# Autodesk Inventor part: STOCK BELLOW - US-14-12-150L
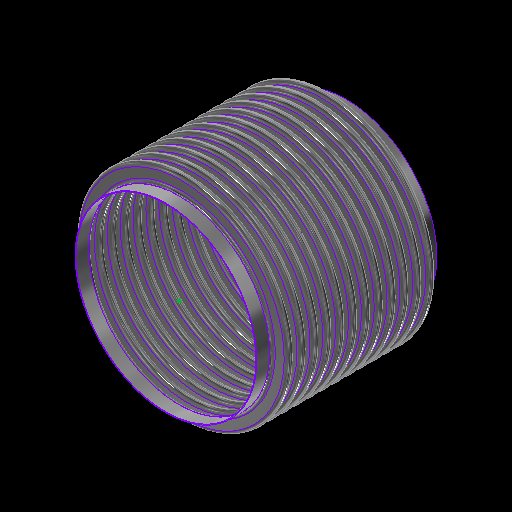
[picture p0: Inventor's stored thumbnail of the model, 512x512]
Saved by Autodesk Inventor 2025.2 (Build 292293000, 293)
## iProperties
Category: 16 GA (0.060 THICK)
RuleStatus: InUse
Created: 2024-01
Part Number: STOCK BELLOW - US-14-12-150L
Project: =STOCK BELLOWS: <Stock Number><SFILL>
Material: ASTM A240-304
Description: =STOCK BELLOWS: <Stock Number>, <SID_> I.D., <SOD_> O.D., <SPLY_> PLY, <Category>, <SNET_CONS> CONS.<PITCH_><STANGENT_> TANGENT<SFILL>
Document SubType Name: Sheet Metal
Designer: GS
Stock Number: U.S-14-12-150L
Surface Area: 23132.1 cm^2
Volume: 1754.85 cm^3
Sheet Metal Rule: Default
Appearance: STAINLESS STEEL
Mass: 14139.3 g
Density: 8.05729 g/cm^3
THK: 0.036
ID: 3.500
OD: 4.250
CONS_: 2
PITCH: 0.500
TANGENT: 0.500
BELLOWS_UPSET: 0.000
d79: 1.000
d82: 1.000
d83: 26.000
d84: 24.000
d174: 8
d214: 8
STHK_: 0.060
SID_: 14.000
SOD_: 16.500
SPITCH_: 1.000
STANGENT__: 1.000
SBELLOWS_UPSET_: 0.000
SDIFF_TAN: 1.000
d252: 2
d275: 2
d287: 0.050
d289: 0.500
d290: 0.000
SOD_NECK: 14 1/8
PLY: 1
PSET: 4.178
PBAR: 1.035
COUNTER: 1.500
NET_TUBE: 3.071
CONS: 2
S_CONS: 0
NET_CONS: 2
ID_M: 88.90 mm
OD_M: 107.95 mm
THK_M: 0.91 mm
ID_U: 3.500 in
OD_U: 4.250 in
THK_U: 0.036 in
TANGENT2: 0.500
TAN_TO_TAN: 1.000 in
d80: 2.571
d81: 10
SID: 2.375
SCONS_: 12
SPITCH: 0.250
STANGENT_: 1.000
SBELLOWS_UPSET: 0.000
SNET_CONS: 12
SS_CONS: 0
SCONS: 8
d190: 8
d191: 1
d192: 1
d193: 8
d194: 0
SIZE: 14.00
PRESSURE: 150
d230: 8
STANGENT: 4.000
SPLY_: 1
d233: 8
d234: 0
d263: 2
d265: 1
d268: 2
d269: 0
d286: 2
d288: 1
d291: 2
d292: 0
SREROLL: 0.750
BLETP: 1.000 ul
PRES_Copy: 85
MATTABLE: 20 GA (0.036 THICK)
PART_NUMBER: U.S-14-12-150L
PITCH_: =, <SPITCH_> PITCH,
CFILL: .
SFILL: .
MESH: ,
COMP: 2.3
EXT: 1.15
LAT: 0.60
ANG: 573
ASR: 2596
LSR: 5659
ANSR: 1185
PRES: 150
COMPM: 23.0
EXTM: 11.5
LATM: 6.00
ASRM: 454.637
PRESM: 10.342
LSRM: 991.061
ANSRM: 207.529
TEMPMIN: 20
TEMPMAX: 800
TEMPMINM: -7
TEMPMAXM: 427
WEIGHTM: 14.139
WEIGHT: 31.172
Author: GS
Keywords: 20 GA (0.036 THICK)
Comments: =STOCK BELLOW - <STOCK NUMBER>
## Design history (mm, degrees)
sketch "Sketch2"
  geometry: L1 (0, -177.245)-(0, 562.856) reference; L2 (45.364, 0)-(44.45, 0); L3 (48.082, -2.718)-(50.343, -2.718); L4 (48.082, -3.632)-(50.343, -3.632); L5 (50.343, -9.982)-(48.082, -9.982); L6 (50.343, -9.068)-(48.082, -9.068); L7 (45.364, -12.7)-(44.45, -12.7); L8 (48.082, 0)-(48.082, -12.7); L9 (50.343, -6.35)-(53.975, -6.35); L10 (44.45, 0)-(44.45, -12.7); L11 (20.376, 102.841)-(20.376, 101.926); L12 (58.262, 457.127)-(58.262, 349.177); L13 (58.262, 444.427)-(58.262, 336.477); L14 (93.133, -58.817)-(93.133, -71.517); L15 (118.746, -66.401)-(118.746, -66.401); L16 (50.343, -9.068)-(50.343, -9.982); L17 (48.082, -9.068)-(48.082, -9.982); L18 (48.082, -9.525)-(50.343, -9.525); L19 (53.975, 0)-(53.975, -12.7); L20 (-50.343, -9.068)-(-50.343, -9.982); L21 (-50.343, -2.718)-(-48.082, -2.718); L22 (-50.343, -3.632)-(-48.082, -3.632); L23 (-48.082, -9.068)-(-50.343, -9.068); L24 (-50.343, -9.525)-(-48.082, -9.525); L25 (-48.082, -9.982)-(-50.343, -9.982); L26 (-48.082, -9.068)-(-48.082, -9.982); L27 (-44.45, 0.653)-(-44.45, -12.047); L28 (-48.082, -6.35)-(-44.45, -6.35); L29 (-50.343, 0.653)-(-50.343, -12.7); L30 (-53.061, 0)-(-53.975, 0); L31 (-53.975, 0)-(-53.975, -12.7); L32 (-53.061, -12.7)-(-53.975, -12.7); A1 r 2.718 centre (48.082, 0) between (45.364, 0) and (48.082, -2.718); A2 r 3.632 centre (48.082, 0) between (44.45, 0) and (48.082, -3.632); A3 r 3.632 centre (50.343, -6.35) between (50.343, -9.982) and (50.343, -2.718); A4 r 2.718 centre (50.343, -6.35) between (50.343, -9.068) and (50.343, -3.632); A5 r 2.718 centre (48.082, -12.7) between (48.082, -9.982) and (45.364, -12.7); A6 r 3.632 centre (48.082, -12.7) between (48.082, -9.068) and (44.45, -12.7); A7 r 3.175 centre (50.343, -6.35) between (50.343, -9.525) and (53.518, -6.35); A8 r 3.175 centre (48.082, -12.7) between (48.082, -9.525) and (44.907, -12.7); A9 r 2.718 centre (-50.343, -12.7) between (-50.343, -9.982) and (-53.061, -12.7); A10 r 2.718 centre (-48.082, -6.35) between (-48.082, -9.068) and (-48.082, -3.632); A11 r 3.175 centre (-48.082, -6.35) between (-48.082, -9.525) and (-44.907, -6.35); A12 r 3.632 centre (-48.082, -6.35) between (-48.082, -9.982) and (-48.082, -2.718); A13 r 3.175 centre (-50.343, -12.7) between (-50.343, -9.525) and (-53.518, -12.7); A14 r 3.632 centre (-50.343, -12.7) between (-50.343, -9.068) and (-53.975, -12.7); A15 r 2.718 centre (-50.343, 0) between (-53.061, 0) and (-50.343, -2.718); A16 r 3.632 centre (-50.343, 0) between (-53.975, 0) and (-50.343, -3.632); 10 further points
  constraints: 62 end point, 38 point on circle, 20 tangent, 16 centre point, 12 parallel, 9 midpoint, 7 vertical, 6 coincident, 6 concentric, 6 point on line, 4 equal radius, 4 perpendicular, 3 horizontal, 1 collinear, 1 horizontal alignment, 10 other
  dimensions: "THK" = 0.9144 distance of L11.start L11.end; "ID" = 88.9 distance of L11.end point (20.376, 13.026); "OD" = 107.95 distance of L12.start L12.end; "PITCH" = 12.7 distance of L12.start L13.start; "TANGENT" = 12.7 distance of L14.start L14.end; "BELLOWS_UPSET" = 0 distance of L15.start L15.end; "d43" = 88.9 diameter of L10 L1 (= ID); "d44" = 107.95 diameter of L9.end L1 (= OD); "d45" = 0.9144 distance between parallel lines of L5 L6 (computed from THK, PLY); "d46" = 3.6322 radius of A3 (computed from PITCH, THK, PLY); "UPSET_PITCH" = 12.7 distance of L2.end L7.end (derived); "SIDEWALL_ANGLE" = 360 deg dimension on L3 L9 (derived); "CON_GAP" = 5.4356 distance of point (48.082, -9.068) point (48.082, -3.632) (derived); "TAN1" = 4.98728 dimension on A8 (derived); "TAN2" = 4.98728 dimension on A7 (derived); "LEG1" = 2.2606 distance of L18.start L18.end (derived); "d278" = 0.9144 distance between parallel lines of L25 L23 (derived); "d279" = 3.6322 radius of A12 (derived); "d280" = 12.7 distance of L30.end L31.end (derived); "d281" = 360 deg dimension on L21 L28 (derived); "d282" = 5.4356 distance of point (-50.343, -9.068) point (-50.343, -3.632) (derived); "d283" = 4.98728 dimension on A13 (derived); "d284" = 4.98728 dimension on A11 (derived); "d285" = 2.2606 distance of L24.start L24.end (derived); "d293" = 88.9 diameter of L27 L1 (derived); "d294" = 107.95 diameter of L31 L1 (derived)
  node "Sketch Rectangular Pattern1" dims "d31" = 25.4, "ID" = 88.9
  node "Sketch Rectangular Pattern2" dims "d39" = 25.4, "PITCH" = 12.7
revolve "CONS" stored, may be unused: angle "d48" = 90 deg
node "BELLOW MIDPLANE"
pattern_linear "Rectangular Pattern2" dims "d52" = 12.7 (= UPSET_PITCH)
sketch "Sketch5"
  geometry: C1 r 45.364 at (0, 0) reference; C2 r 44.45 at (0, 0) reference
extrude "TANGENT" new body sketch "Sketch5" distance "d53" = 12.7 (= TANGENT); taper "d54" = 0 deg
revolve "SAMETAN" stored, may be unused: angle "d65" = 90 deg
revolve "DIFFTAN" stored, may be unused: angle "d70" = 90 deg
sketch "Sketch9"
  geometry: L1 (53.319, 0)-(-53.319, 0) reference; L2 (0, -17.78)-(0, 17.78) reference; L3 (38.085, 0)-(-38.085, 0); L4 (38.085, -11.906)-(38.085, 11.906); L5 (25.385, -11.906)-(25.385, 11.906); L6 (13.15, 11.906)-(13.15, -11.906); L7 (-25.385, -11.906)-(-25.385, 11.906); L8 (-38.085, -11.906)-(-38.085, 11.906); L9 (37.291, -11.906)-(37.291, 11.906); L10 (38.085, -11.906)-(37.291, -11.906); L11 (38.085, 11.906)-(37.291, 11.906); L12 (13.546, 11.906)-(12.753, 11.906); L13 (12.753, 11.906)-(12.753, -11.906); L14 (12.753, -11.906)-(13.546, -11.906); L15 (13.546, -11.906)-(13.546, 11.906); L16 (-13.546, 11.906)-(-13.546, -11.906); L17 (-13.15, 11.906)-(-13.15, -11.906); L18 (-13.546, -11.906)-(-12.753, -11.906); L19 (-12.753, -11.906)-(-12.753, 11.906); L20 (-12.753, 11.906)-(-13.546, 11.906); L21 (-38.085, -11.906)-(-37.291, -11.906); L22 (-37.291, -11.906)-(-37.291, 11.906); L23 (-37.291, 11.906)-(-38.085, 11.906); L24 (-38.085, 11.906)-(-38.085, -11.906); L25 (38.085, -0.397)-(-38.085, -0.397); L26 (-38.085, -0.397)-(-38.085, 0.397); L27 (-38.085, 0.397)-(38.085, 0.397); L28 (38.085, 0.397)-(38.085, -0.397); L29 (-38.085, 11.906)-(38.085, 11.906); L30 (38.085, 11.906)-(38.085, 12.7); L31 (38.085, 12.7)-(-38.085, 12.7); L32 (-38.085, 12.7)-(-38.085, 11.906); L33 (38.085, -11.906)-(-38.085, -11.906); L34 (-38.085, -11.906)-(-38.085, -12.7); L35 (-38.085, -12.7)-(38.085, -12.7); L36 (38.085, -12.7)-(38.085, -11.906); 30 further points
  constraints: 68 end point, 13 midpoint, 13 parallel, 8 horizontal, 7 perpendicular, 6 equal length, 3 point on line, 2 vertical, 14 other
  dimensions: "d115" = 23.8125 distance of L4.start L4.end (derived); "d116" = 12.7 distance between parallel lines of L4 L5 (derived); "d117" = 12.23516 distance between parallel lines of L5 L6 (derived); "d125" = 38.53427 distance between parallel lines of L7 L6 (derived); "d127" = 12.7 distance between parallel lines of L8 L7 (derived); "d128" = 24.93516 distance between parallel lines of L6 L4 (derived); "d130" = 76.16943 distance between parallel lines of L8 L4 (derived); "RULER_THK" = 0.79375 distance between parallel lines of L4 L9; "d135" = 0.79375 distance of L13.end L14.end (derived); "d138" = 26.29911 distance of L13.end L16.end (derived); "d143" = 0.79375 distance of L22.end L8.end (derived); "d144" = 0.79375 distance between parallel lines of L27 L25 (derived)
extrude "RULER" join sketch "Sketch9" distance "d149" = 0.79375 (derived); taper "d150" = 0 deg
extrude "BARS" join sketch "Sketch9" distance "d151" = 0.79375 (derived); taper "d152" = 0 deg
pattern_linear "Rectangular Pattern4" dims "d155" = 26.29911 (derived)
sketch "Sketch13"
  geometry: L1 (93.149, -52.467)-(93.149, -77.867); L2 (179.324, 0)-(177.8, 0); L3 (179.324, -25.4)-(177.8, -25.4); L4 (202.438, -19.812)-(184.912, -19.812); L5 (202.438, -18.288)-(184.912, -18.288); L6 (202.438, -12.7)-(209.55, -12.7); L7 (184.912, -5.588)-(202.438, -5.588); L8 (184.912, 0)-(184.912, -25.4); L9 (177.8, 0)-(177.8, -25.4); L10 (58.254, -77.331)-(58.254, -496.431); L11 (58.254, -102.731)-(58.254, -521.831); L12 (58.254, -153.531)-(58.254, -572.631); L13 (58.254, -178.931)-(58.254, -598.031); L14 (58.254, -204.331)-(58.254, -623.431); L15 (58.254, -229.731)-(58.254, -648.831); L16 (58.254, -255.131)-(58.254, -674.231); L17 (58.254, -128.131)-(58.254, -547.231); L18 (20.376, 103.45)-(20.376, 101.926); L19 (184.912, -7.112)-(202.438, -7.112); L20 (0, -829.767)-(0, 258.986) reference; L21 (-41.91, 0)-(251.46, 0) reference; A1 r 5.588 centre (184.912, 0) between (179.324, 0) and (184.912, -5.588); A2 r 5.588 centre (184.912, -25.4) between (184.912, -19.812) and (179.324, -25.4); A3 r 7.112 centre (184.912, -25.4) between (184.912, -18.288) and (177.8, -25.4); A4 r 5.588 centre (202.438, -12.7) between (202.438, -18.288) and (202.438, -7.112); A5 r 7.112 centre (202.438, -12.7) between (202.438, -19.812) and (202.438, -5.588); A6 r 7.112 centre (184.912, 0) between (177.8, 0) and (184.912, -7.112); 6 further points; 1 other entity
  constraints: 38 end point, 15 point on circle, 9 tangent, 6 centre point, 6 parallel, 5 vertical alignment, 4 point on line, 4 vertical, 3 coincident, 3 concentric, 2 collinear, 2 equal radius, 1 horizontal, 1 perpendicular, 23 other
  dimensions: "SBELLOWS_UPSET_" = 0 distance of point (118.762, -66.401) point (118.762, -66.401); "STOTAL_THK_BELLOW__" = 1.524 distance between parallel lines of L4 L5 (derived); "d224" = 7.112 radius of A5 (derived); "d225" = 25.4 distance of L2.end L3.end (derived); "SSIDEWALL_ANGLE_" = 360 deg dimension on L7 L6 (derived); "SSCON_GAP_" = 11.176 distance of point (184.912, -18.288) point (184.912, -7.112) (derived); "d235" = 355.6 diameter of L9 L20 (derived); "d236" = 419.1 diameter of L6.end L20 (derived)
  node "Sketch Rectangular Pattern4" dims "d228" = 25.4
  node "Sketch Rectangular Pattern5" dims "d229" = 25.4
revolve "SBELLOW" stored, may be unused: angle "d197" = 90 deg
pattern_linear "Rectangular Pattern5" dims "d204" = 25.4 (derived)
revolve "STANGENT" stored, may be unused: angle "d240" = 90 deg
revolve "SSAMETAN" stored, may be unused: angle "d241" = 90 deg
revolve "SDIFFTAN" stored, may be unused: angle "d246" = 90 deg
revolve "INVCON" stored, may be unused: angle "d295" = 90 deg
pattern_linear "Rectangular Pattern6" dims "d298" = 12.7 (derived)
revolve "INVTANGENT" stored, may be unused: angle "d302" = 90 deg
revolve "INVSAMETAN" stored, may be unused: angle "d307" = 90 deg
revolve "INVDIFFTAN" stored, may be unused: angle "d312" = 90 deg
sketch "ID BELLOW MOUNT CALC"
  geometry: L1 (44.45, 0)-(38.1, 0); L2 (38.1, 0)-(38.1, 12.7); L3 (38.1, 12.7)-(44.45, 12.7); L4 (44.45, 12.7)-(44.45, 0); L5 (36.513, 12.7)-(35.598, 12.7); L6 (35.598, 12.7)-(35.598, 0); L7 (35.598, 0)-(36.513, 0); L8 (36.513, 0)-(36.513, 12.7); L9 (0, -2.54)-(0, 15.24) reference; L10 (-8.89, 0)-(53.34, 0) reference; 1 further point
  constraints: 16 end point, 5 parallel, 2 collinear, 2 horizontal, 2 perpendicular
  dimensions: "d314" = 12.7 distance of L5.end L6.end (derived); "d315" = 0.9144 distance of L5.start L5.end (derived); "IG" = 1.5875 distance between parallel lines of L2 L8; "PIPE_OD" = 88.9 diameter of L4 L9; "PIPE_WALL" = 6.35 distance of L2.end L3.end; "ID_MT_BELLOW" = 71.1962 diameter of L6 L9 (derived)
revolve "CFILL" stored, may be unused: angle "d320" = 90 deg
pattern_linear "Rectangular Pattern7" dims "d323" = 12.7 (derived)
revolve "SFILL" stored, may be unused: angle "d324" = 90 deg
pattern_linear "Rectangular Pattern8" dims "d327" = 25.4 (derived)
node "STOCK BELLOW MIDPLANE"
node "BELLOW"
sketch "Sketch6"
  geometry: L1 (-12.7, 45.364)-(0, 45.364); L2 (0, 45.364)-(0, 44.45); L3 (0, 44.45)-(-12.7, 44.45); L4 (-12.7, 44.45)-(-12.7, 45.364); L5 (10.16, 0)-(-60.96, 0) reference; L6 (-38.1, -89.422)-(-38.1, 153.44) reference; 1 further point
  constraints: 8 end point, 2 parallel, 1 horizontal, 1 perpendicular
  dimensions: "d61" = 12.7 distance of L2.end L3.end (derived); "d62" = 0.9144 distance of L1.end L2.end (derived); "d63" = 88.9 diameter of L3 L5 (derived); "d64" = 25.4 distance between parallel lines of L4 L6 (derived)
sketch "Sketch12"
  geometry: 1 further point
sketch "Sketch14"
  geometry: L1 (-25.4, 179.324)-(0, 179.324); L2 (0, 179.324)-(0, 177.8); L3 (0, 177.8)-(-25.4, 177.8); L4 (-25.4, 177.8)-(-25.4, 179.324); L5 (5.08, 0)-(-30.48, 0) reference; L6 (0, -35.865)-(0, 215.189) reference; 1 further point
  constraints: 8 end point, 2 parallel, 1 collinear, 1 horizontal, 1 perpendicular
  dimensions: "d237" = 1.524 distance of L3.end L1.start (derived); "d238" = 355.6 diameter of L3 L5 (derived); "d239" = 25.4 distance of L1.start L1.end (derived); "SOD_NECK" = 358.648 diameter of L1 L5 (derived)
sketch "Sketch15"
  geometry: L1 (-35.865, 0)-(215.189, 0) reference; L2 (177.8, -304.8)-(179.324, -304.8); L3 (179.324, -304.8)-(179.324, -330.2); L4 (179.324, -330.2)-(177.8, -330.2); L5 (177.8, -330.2)-(177.8, -304.8); L6 (0, -398.78)-(0, 81.28) reference; 1 further point
  constraints: 8 end point, 2 parallel, 1 horizontal, 1 perpendicular
  dimensions: "d205" = 25.4 distance of L4.end L2.start (derived); "d206" = 1.524 distance of L3.end L4.end (derived); "d207" = 355.6 diameter of L5 L6 (derived); "d208" = 304.8 distance between parallel lines of L1 L2 (derived)
node "TANGENT_"
node "SAME_TAN"
sketch "Sketch8"
  geometry: L1 (45.364, -25.4)-(44.45, -25.4); L2 (44.45, -25.4)-(44.45, -38.1); L3 (44.45, -38.1)-(45.364, -38.1); L4 (45.364, -38.1)-(45.364, -25.4); L5 (0, -48.26)-(0, 22.86) reference; L6 (-89.422, 0)-(153.44, 0) reference; 1 further point
  constraints: 8 end point, 2 parallel, 1 horizontal, 1 perpendicular
  dimensions: "d66" = 88.9 diameter of L2 L5 (derived); "TOTAL_THK_BELLOW" = 0.9144 distance of L2.end L3.end (derived); "d68" = 25.4 distance between parallel lines of L1 L6 (derived); "d69" = 12.7 distance of L1.end L2.end (derived)
node "DIFF_TAN"
node "Sketch Rectangular Pattern3" dims "d138" = 26.29911 (derived), "d141" = 25.4
node "SBELLOW_"
node "STANGENT_"
node "SSAME_TAN"
sketch "Sketch16"
  geometry: L1 (179.324, -304.8)-(177.8, -304.8); L2 (177.8, -304.8)-(177.8, -330.2); L3 (177.8, -330.2)-(179.324, -330.2); L4 (179.324, -330.2)-(179.324, -304.8); L5 (0, -398.78)-(0, 81.28) reference; L6 (-35.865, 0)-(215.189, 0) reference; 1 further point
  constraints: 8 end point, 2 parallel, 1 horizontal, 1 perpendicular
  dimensions: "SDIFF_TAN" = 25.4 distance of L3.end L1.start; "d243" = 1.524 distance of L2.end L3.end (derived); "d244" = 304.8 distance between parallel lines of L1 L6 (derived); "d245" = 355.6 diameter of L2 L5 (derived)
node "SDIFF_TAN"
body "Solid15"
sketch "Sketch17"
  geometry: L1 (53.975, 12.7)-(53.061, 12.7); L2 (53.061, 12.7)-(53.061, 0); L3 (53.061, 0)-(53.975, 0); L4 (53.975, 0)-(53.975, 12.7); L5 (0, -2.54)-(0, 15.24) reference; L6 (-10.795, 0)-(64.77, 0) reference; 2 further points
  constraints: 8 end point, 2 parallel, 1 horizontal, 1 midpoint, 1 perpendicular, 1 point on line
  dimensions: "INVTANGENT" = 12.7 distance of L3.end L1.start (derived); "d300" = 0.9144 distance of L1.start L1.end (derived); "d301" = 107.95 diameter of L4 L5 (derived)
body "Solid16"
sketch "Sketch18"
  geometry: L1 (53.975, -25.4)-(53.061, -25.4); L2 (53.061, -25.4)-(53.061, -38.1); L3 (53.061, -38.1)-(53.975, -38.1); L4 (53.975, -38.1)-(53.975, -25.4); L5 (-10.795, 0)-(64.77, 0) reference; L6 (0, -48.26)-(0, 22.86) reference; 1 further point
  constraints: 8 end point, 2 parallel, 1 horizontal, 1 perpendicular
  dimensions: "d303" = 25.4 distance between parallel lines of L1 L5 (derived); "d304" = 12.7 distance of L3.end L1.start (derived); "d305" = 0.9144 distance of L2.end L3.end (derived); "d306" = 107.95 diameter of L4 L6 (derived)
body "Solid17"
sketch "Sketch19"
  geometry: L1 (53.975, -25.4)-(53.061, -25.4); L2 (53.061, -25.4)-(53.061, -38.1); L3 (53.061, -38.1)-(53.975, -38.1); L4 (53.975, -38.1)-(53.975, -25.4); L5 (0, -48.26)-(0, 22.86) reference; L6 (-10.795, 0)-(64.77, 0) reference; 1 further point
  constraints: 8 end point, 2 parallel, 1 horizontal, 1 perpendicular
  dimensions: "d308" = 12.7 distance of L1.end L2.end (derived); "d309" = 107.95 diameter of L4 L5 (derived); "d310" = 0.9144 distance of L2.end L3.end (derived); "d311" = 25.4 distance between parallel lines of L1 L6 (derived)
body "Solid18"
body "Solid19"
body "Solid20"
other parameters: "BMPL" = -152.4, "PSET" = 106.1212 (computed from OD, THK, PLY) [user parameter], "PBAR" = 26.29911 (= 0.570796 x PITCH + OD - ID) [user parameter; used in 1 equation term], "COUNTER" = 15 [user parameter], "NET_TUBE" = 77.99823 (computed from CONS_, PBAR, TANGENT) [user parameter], "S_CONS" = 0 [user parameter; used in 1 equation term], "ID_M" = 88.9 (= ID) [user parameter], "OD_M" = 107.95 (= OD) [user parameter], "THK_M" = 0.9144 (= THK) [user parameter], "ID_U" = 88.9 (= ID) [user parameter], "OD_U" = 107.95 (= OD) [user parameter], "THK_U" = 0.9144 (= THK) [user parameter], "D_UNITS" = 0 [user parameter], "TANGENT2" = 12.7 [user parameter], "TAN_TO_TAN" = 25.4 [user parameter], "OD_NECK" = 90.7288 [user parameter], "d79" = 25.4, "d80" = 65.29823 [user parameter], "d82" = 25.4, "d83" = 660.4, "d84" = 609.6, "sa_0" = 4, "FRAME_THK" = 0.79375 [user parameter], "CON_FLAT" = 12.23516 [user parameter], "SID" = 60.325 [user parameter], "SPITCH" = 6.35 [user parameter], "STANGENT_" = 25.4 [user parameter], "SBELLOWS_UPSET" = 0 [user parameter], "SS_CONS" = 0 [user parameter], "STAN_TO_TAN_" = 304.8 [user parameter], "d100" = 1.524 [user parameter], "d191" = 25.4 [user parameter], "d194" = 0 [user parameter], "STANGENT" = 101.6 [user parameter], "d234" = 0 [user parameter], "SUPSET_PITCH_" = 25.4 [user parameter], "d269" = 0 [user parameter], "d287" = 1.27, "d289" = 12.7, "d290" = 0, "d292" = 0 [user parameter], "Thickness" = 3.048 (derived), "KFactor" = 4.4, "BendRadius" = 3.048 (derived), "BendReliefWidth" = 3.048 (derived), "BendReliefDepth" = 1.524 (derived), "CornerReliefSize" = 12.192 (derived), "SeamGap" = 0.00508, "MinimumRemnant" = 6.096 (derived), "TransitionRadius" = 3.048 (derived), "JacobiRadiusSize" = 3.048 (derived), "GapSize" = 3.048 (derived), "SREROLL" = 19.05 [user parameter], "CUR_STK_PITCH" = 25.4 [user parameter], "d328" = -152.4 (derived), "ASR" = 25960 [user parameter], "LSR" = 56590 [user parameter], "ANSR" = 11850 [user parameter], "BLETP" = 1 [user parameter], "ASRM" = 4546.3748 [user parameter], "PRESM" = 103.41975 [user parameter], "LSRM" = 9910.6067 [user parameter], "ANSRM" = 2075.2905 [user parameter], "TEMPMIN" = 2664.83333 [user parameter], "TEMPMAX" = 6998.16667 [user parameter], "TEMPMINM" = 2664.83333 [user parameter], "TEMPMAXM" = 6998.16667 [user parameter], "WEIGHT" = 141.393 [user parameter], "WEIGHTM" = 0.14139 [user parameter]
